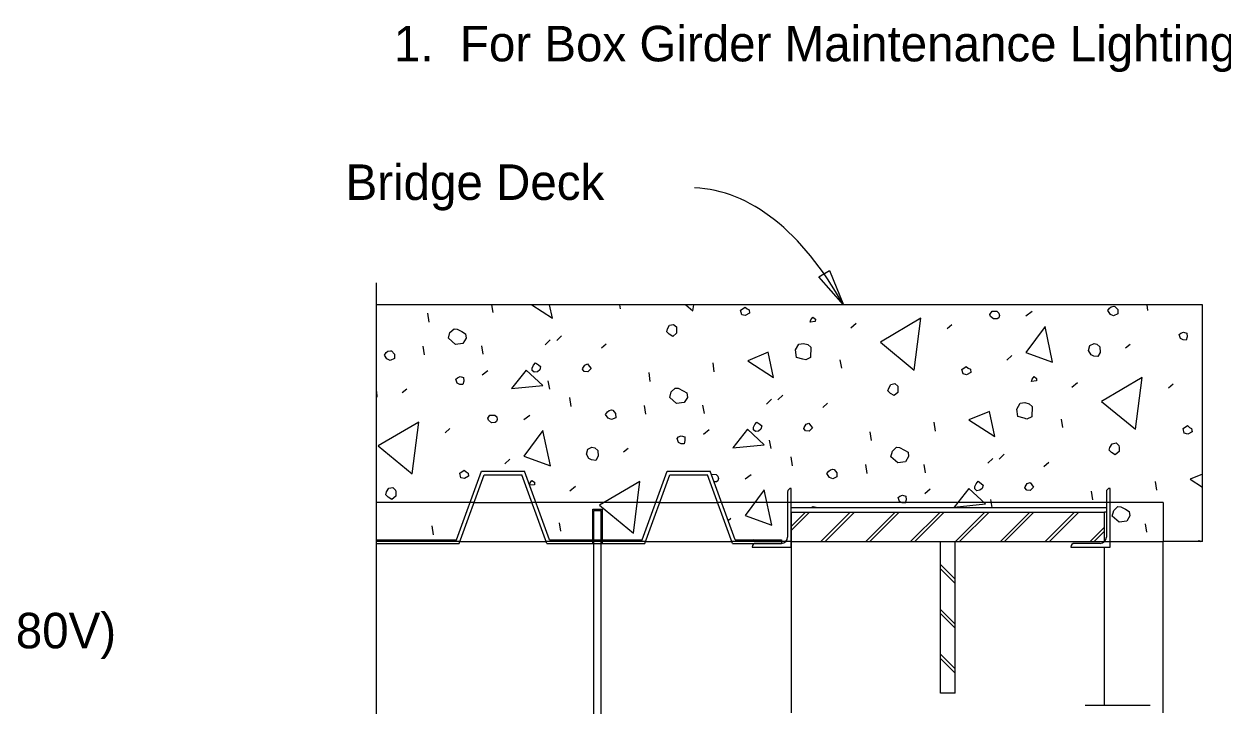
# Model space of a CAD drawing. Extents: x 0 to 30.8, y 0 to 21.2.
# Drawn here: x 21.15 to 26.25, y 6.83 to 9.73 of the extents above; entities that cross this region are included whole.
import ezdxf

# ---------------------------------------------------------------- set-up
doc = ezdxf.new("R2010")
doc.units = 0
for name, color, linetype in [('Dimension', 7, 'Continuous'), ('Lighting', 7, 'Continuous'), ('Miscellaneous', 7, 'Continuous'), ('SteelGirder', 7, 'Continuous'), ('SteelGirder_h', 7, 'Continuous'), ('SupstrConc', 7, 'Continuous'), ('TextStructures', 7, 'Continuous')]:
    doc.layers.add(name, color=color, linetype=linetype)

msp = doc.modelspace()

# ---------------------------------------------------------------- linework, layer by layer
at = {"layer": 'Dimension'}
msp.add_lwpolyline([(24.6432, 8.5353), (24.5386, 8.6542), (24.5836, 8.682)], close=True, dxfattribs=at)
msp.add_lwpolyline([(22.6555, 6.3623), (22.6555, 8.629)], dxfattribs=at)
msp.add_ellipse((23.8981, 6.6665), major_axis=(-0.1111, -2.3674), ratio=0.464296, start_param=2.502126, end_param=3.141581, dxfattribs=at)
at = {"layer": 'Lighting'}
msp.add_line((25.6718, 6.8313), (25.9492, 6.8313), dxfattribs=at)
at = {"layer": 'Miscellaneous'}
for p, q in [((23.1517, 8.5027), (23.147, 8.5353)), ((23.6941, 8.5179), (23.6911, 8.5353)), ((25.939, 8.5116), (25.9355, 8.5353)), ((22.8793, 8.4618), (22.8739, 8.4995)), ((25.4459, 8.5066), (25.4201, 8.4876)), ((24.6973, 8.4561), (24.6739, 8.4365)), ((25.1047, 8.4505), (25.0844, 8.4326)), ((23.3947, 8.3858), (23.3738, 8.3656)), ((23.4435, 8.4038), (23.4226, 8.3836)), ((23.6333, 8.3685), (23.613, 8.3506)), ((25.8637, 8.3661), (25.8441, 8.3507)), ((22.86, 8.3221), (22.8546, 8.3598)), ((23.1093, 8.3252), (23.1032, 8.3604)), ((25.3596, 8.32), (25.3387, 8.2998)), ((24.0935, 8.2504), (24.088, 8.2881)), ((24.6359, 8.2655), (24.6298, 8.3008)), ((23.1293, 8.2551), (23.1059, 8.2355)), ((23.393, 8.1767), (23.3869, 8.2119)), ((23.8211, 8.2095), (23.8157, 8.2472)), ((22.7848, 8.1766), (22.7651, 8.1611)), ((25.6391, 8.2038), (25.6157, 8.1841)), ((26.0465, 8.1981), (26.0262, 8.1803)), ((23.4846, 8.103), (23.4791, 8.1406)), ((24.3365, 8.1335), (24.3155, 8.1132)), ((24.3853, 8.1515), (24.3643, 8.1312)), ((24.5751, 8.1161), (24.5548, 8.0983)), ((23.3087, 8.0647), (23.2829, 8.0457)), ((23.8018, 8.0697), (23.7963, 8.1074)), ((24.0511, 8.0728), (24.045, 8.1081)), ((22.9675, 8.0086), (22.9472, 7.9907)), ((25.0352, 7.998), (25.0298, 8.0357)), ((25.5776, 8.0132), (25.5716, 8.0484)), ((24.0711, 8.0027), (24.0477, 7.9831)), ((24.3348, 7.9243), (24.3287, 7.9596)), ((24.7629, 7.9571), (24.7574, 7.9948)), ((23.7265, 7.9242), (23.7069, 7.9088)), ((23.2224, 7.8781), (23.2015, 7.8579)), ((24.4263, 7.8506), (24.4209, 7.8883)), ((24.7435, 7.8174), (24.7381, 7.8551)), ((24.9928, 7.8205), (24.9868, 7.8557)), ((25.2783, 7.8811), (25.2573, 7.8609)), ((25.3271, 7.8991), (25.3061, 7.8789)), ((25.5169, 7.8638), (25.4966, 7.8459)), ((22.996, 7.5353), (23.1022, 7.8271)), ((23.007, 7.5197), (23.1132, 7.8115)), ((23.1022, 7.8271), (23.2855, 7.8271)), ((23.1132, 7.8115), (23.2746, 7.8115)), ((23.3808, 7.5197), (23.2746, 7.8115)), ((23.3917, 7.5353), (23.2855, 7.8271)), ((23.7865, 7.5353), (23.8927, 7.8271)), ((23.7974, 7.5197), (23.9036, 7.8115)), ((23.8927, 7.8271), (24.076, 7.8271)), ((23.9036, 7.8115), (24.0651, 7.8115)), ((24.1712, 7.5197), (24.0651, 7.8115)), ((24.1822, 7.5353), (24.076, 7.8271)), ((24.2504, 7.8123), (24.2246, 7.7934)), ((23.5019, 7.7619), (23.4785, 7.7422)), ((24.4212, 7.5041), (24.4212, 7.7541)), ((25.7779, 7.5041), (25.7779, 7.7541)), ((25.977, 7.7457), (25.9716, 7.7834)), ((24.4056, 7.7385), (24.4056, 7.5458)), ((25.0129, 7.7504), (24.9895, 7.7308)), ((25.2764, 7.6731), (25.2705, 7.7072)), ((25.7046, 7.7048), (25.6992, 7.7425)), ((25.7623, 7.7384), (25.7623, 7.5457)), ((24.4212, 7.5922), (24.4814, 7.6523)), ((24.4212, 7.5745), (24.4991, 7.6523)), ((24.4213, 7.6731), (25.7623, 7.6731)), ((24.5473, 7.5273), (24.6723, 7.6523)), ((24.565, 7.5273), (24.69, 7.6523)), ((24.7382, 7.5273), (24.8632, 7.6523)), ((24.7559, 7.5273), (24.8809, 7.6523)), ((24.9291, 7.5273), (25.0541, 7.6523)), ((24.9468, 7.5273), (25.0718, 7.6523)), ((25.1201, 7.5273), (25.2451, 7.6523)), ((25.1377, 7.5273), (25.2627, 7.6523)), ((25.311, 7.5273), (25.436, 7.6523)), ((25.3287, 7.5273), (25.4537, 7.6523)), ((25.5019, 7.5273), (25.6269, 7.6523)), ((25.5196, 7.5273), (25.6446, 7.6523)), ((25.7623, 7.6523), (25.7547, 7.6523)), ((23.4404, 7.5713), (23.4344, 7.6065)), ((24.1642, 7.6258), (24.1531, 7.6151)), ((25.9346, 7.5681), (25.9285, 7.6034)), ((22.898, 7.5561), (22.8926, 7.5938)), ((25.6928, 7.5273), (25.7546, 7.5891)), ((25.7105, 7.5273), (25.7546, 7.5715)), ((22.6555, 7.5353), (22.996, 7.5353)), ((22.6555, 7.5197), (23.007, 7.5197)), ((23.3808, 7.5197), (23.7974, 7.5197)), ((23.3917, 7.5353), (23.7865, 7.5353)), ((24.1712, 7.5197), (24.3795, 7.5197)), ((24.1822, 7.5353), (24.3795, 7.5353)), ((24.2545, 7.5041), (24.4212, 7.5041)), ((24.3795, 7.5197), (24.2702, 7.5197)), ((24.3795, 7.5353), (24.3795, 7.5197)), ((25.6113, 7.5041), (25.7779, 7.5041)), ((25.7363, 7.5197), (25.6269, 7.5197)), ((25.1192, 7.3668), (25.0568, 7.4292)), ((25.1192, 7.3491), (25.0568, 7.4115)), ((25.1192, 7.1759), (25.0568, 7.2383)), ((25.1192, 7.1582), (25.0568, 7.2206)), ((25.1192, 6.9849), (25.0568, 7.0473)), ((25.1192, 6.9673), (25.0568, 7.0297))]:
    msp.add_line(p, q, dxfattribs=at)
for points in [[(23.3167, 8.5353), (23.4042, 8.4791)], [(23.4042, 8.4791), (23.392, 8.5353)], [(23.9722, 8.5353), (24.0026, 8.5102)], [(24.0026, 8.5102), (24.0058, 8.5353)], [(24.2432, 8.5001), (24.2248, 8.4895), (24.2103, 8.4934), (24.2052, 8.5129), (24.2242, 8.5259), (24.2326, 8.5185), (24.2416, 8.5135), (24.2432, 8.5001), (24.2445, 8.505)], [(25.8105, 8.515), (25.8108, 8.4968), (25.793, 8.4886), (25.7792, 8.4949), (25.7679, 8.5109), (25.776, 8.5216), (25.7828, 8.5276), (25.7937, 8.5298), (25.7986, 8.5285), (25.8105, 8.515)], [(24.5234, 8.4639), (24.5021, 8.4618), (24.5047, 8.4715), (24.5128, 8.4823), (24.5235, 8.4742), (24.5234, 8.4639)], [(24.9444, 8.2579), (24.9724, 8.4782), (24.8002, 8.3768), (24.9444, 8.2579)], [(25.3041, 8.4799), (25.298, 8.4763), (25.2822, 8.4754), (25.2696, 8.4865), (25.2668, 8.495), (25.2755, 8.5082), (25.2961, 8.5079), (25.3045, 8.5005), (25.3067, 8.4895), (25.3041, 8.4799)], [(23.0371, 8.3937), (23.0233, 8.3715), (22.9911, 8.3672), (22.9618, 8.3931), (22.9683, 8.4173), (22.9856, 8.4334), (22.9983, 8.4325), (23.0187, 8.4219), (23.0343, 8.4125), (23.0371, 8.3937)], [(23.9328, 8.4332), (23.9331, 8.415), (23.9165, 8.4013), (23.9009, 8.4107), (23.8908, 8.4212), (23.894, 8.4332), (23.9033, 8.4488), (23.9198, 8.4522), (23.9323, 8.4411), (23.9328, 8.4332)], [(25.5332, 8.2917), (25.5012, 8.4426), (25.4199, 8.3324), (25.5332, 8.2917)], [(26.1057, 8.3997), (26.1018, 8.3852), (26.0891, 8.386), (26.0776, 8.3917), (26.0719, 8.4087), (26.0786, 8.4147), (26.0902, 8.4193), (26.1047, 8.4155), (26.1057, 8.3997)], [(24.5046, 8.355), (24.5032, 8.3114), (24.4824, 8.3014), (24.4704, 8.3047), (24.4438, 8.3118), (24.4395, 8.344), (24.4538, 8.3686), (24.4727, 8.3713), (24.492, 8.3662), (24.5046, 8.355)], [(25.7344, 8.3568), (25.7358, 8.3331), (25.7258, 8.3151), (25.7083, 8.3172), (25.6969, 8.3229), (25.6862, 8.3412), (25.6921, 8.363), (25.7098, 8.3712), (25.7219, 8.3679), (25.7344, 8.3568)], [(22.7315, 8.3254), (22.7318, 8.3072), (22.7141, 8.2991), (22.7002, 8.3054), (22.689, 8.3213), (22.697, 8.3321), (22.7038, 8.338), (22.7147, 8.3403), (22.7196, 8.339), (22.7315, 8.3254)], [(24.3459, 8.2267), (24.3229, 8.3338), (24.2356, 8.2977), (24.3459, 8.2267)], [(23.3501, 8.258), (23.3403, 8.2503), (23.3269, 8.2487), (23.3185, 8.2561), (23.3187, 8.2664), (23.3244, 8.2779), (23.3324, 8.2887), (23.3456, 8.2799), (23.354, 8.2725), (23.3501, 8.258)], [(23.5691, 8.2641), (23.5549, 8.2497), (23.5398, 8.2512), (23.5321, 8.261), (23.5334, 8.2659), (23.5421, 8.2791), (23.5537, 8.2837), (23.5614, 8.2739), (23.5691, 8.2641)], [(25.185, 8.2478), (25.1666, 8.2372), (25.1521, 8.2411), (25.147, 8.2606), (25.166, 8.2736), (25.1744, 8.2662), (25.1834, 8.2612), (25.185, 8.2478), (25.1863, 8.2526)], [(23.0267, 8.2101), (23.0228, 8.1956), (23.0101, 8.1964), (22.9987, 8.2021), (22.9929, 8.2192), (22.9996, 8.2251), (23.0112, 8.2298), (23.0257, 8.2259), (23.0267, 8.2101)], [(23.3636, 8.1923), (23.2931, 8.2578), (23.2305, 8.1788), (23.3636, 8.1923)], [(25.4651, 8.2115), (25.4439, 8.2095), (25.4465, 8.2191), (25.4545, 8.2299), (25.4653, 8.2218), (25.4651, 8.2115)], [(25.8862, 8.0055), (25.9141, 8.2258), (25.742, 8.1244), (25.8862, 8.0055)], [(22.6555, 8.1661), (22.6569, 8.1436), (22.6555, 8.1411)], [(23.9788, 8.1413), (23.9651, 8.1191), (23.9329, 8.1148), (23.9036, 8.1408), (23.9101, 8.1649), (23.9273, 8.181), (23.9401, 8.1802), (23.9605, 8.1695), (23.9761, 8.1602), (23.9788, 8.1413)], [(24.8746, 8.1808), (24.8749, 8.1626), (24.8583, 8.149), (24.8427, 8.1583), (24.8325, 8.1688), (24.8358, 8.1809), (24.8451, 8.1965), (24.8616, 8.1999), (24.8741, 8.1887), (24.8746, 8.1808)], [(25.4463, 8.1027), (25.445, 8.0591), (25.4242, 8.0491), (25.4121, 8.0523), (25.3856, 8.0595), (25.3813, 8.0917), (25.3956, 8.1163), (25.4145, 8.119), (25.4338, 8.1138), (25.4463, 8.1027)], [(23.1669, 8.038), (23.1608, 8.0344), (23.145, 8.0335), (23.1325, 8.0446), (23.1296, 8.0531), (23.1383, 8.0663), (23.1589, 8.066), (23.1673, 8.0586), (23.1695, 8.0476), (23.1669, 8.038)], [(23.6733, 8.0731), (23.6736, 8.0549), (23.6558, 8.0467), (23.642, 8.053), (23.6307, 8.069), (23.6388, 8.0797), (23.6456, 8.0857), (23.6565, 8.0879), (23.6614, 8.0866), (23.6733, 8.0731)], [(25.2877, 7.9744), (25.2647, 8.0815), (25.1773, 8.0454), (25.2877, 7.9744)], [(22.8072, 7.816), (22.8352, 8.0363), (22.6631, 7.9348), (22.8072, 7.816)], [(24.2919, 8.0057), (24.2821, 7.998), (24.2687, 7.9964), (24.2603, 8.0038), (24.2605, 8.0141), (24.2661, 8.0255), (24.2742, 8.0363), (24.2874, 8.0276), (24.2958, 8.0202), (24.2919, 8.0057)], [(24.5109, 8.0117), (24.4967, 7.9974), (24.4816, 7.9989), (24.4739, 8.0087), (24.4752, 8.0135), (24.4839, 8.0267), (24.4955, 8.0314), (24.5032, 8.0215), (24.5109, 8.0117)], [(26.1268, 7.9954), (26.1084, 7.9848), (26.0939, 7.9887), (26.0888, 8.0082), (26.1078, 8.0212), (26.1162, 8.0138), (26.1252, 8.0088), (26.1268, 7.9954), (26.1281, 8.0003)], [(23.396, 7.8497), (23.364, 8.0007), (23.2827, 7.8905), (23.396, 7.8497)], [(23.9685, 7.9578), (23.9646, 7.9433), (23.9519, 7.9441), (23.9404, 7.9497), (23.9347, 7.9668), (23.9414, 7.9728), (23.953, 7.9774), (23.9675, 7.9735), (23.9685, 7.9578)], [(24.3053, 7.94), (24.2349, 8.0054), (24.1723, 7.9264), (24.3053, 7.94)], [(23.5972, 7.9149), (23.5986, 7.8912), (23.5886, 7.8732), (23.5711, 7.8753), (23.5597, 7.881), (23.549, 7.8993), (23.5549, 7.9211), (23.5726, 7.9292), (23.5847, 7.926), (23.5972, 7.9149)], [(24.9206, 7.889), (24.9069, 7.8668), (24.8747, 7.8625), (24.8454, 7.8884), (24.8519, 7.9126), (24.8691, 7.9287), (24.8818, 7.9278), (24.9023, 7.9172), (24.9179, 7.9078), (24.9206, 7.889)], [(25.8164, 7.9285), (25.8167, 7.9103), (25.8001, 7.8966), (25.7844, 7.906), (25.7743, 7.9165), (25.7775, 7.9285), (25.7869, 7.9441), (25.8033, 7.9475), (25.8159, 7.9364), (25.8164, 7.9285)], [(23.0478, 7.8059), (23.0294, 7.7953), (23.0149, 7.7992), (23.0098, 7.8186), (23.0288, 7.8317), (23.0372, 7.8242), (23.0462, 7.8192), (23.0478, 7.8059), (23.0491, 7.8107)], [(24.0808, 7.814), (24.1007, 7.8136), (24.109, 7.8062), (24.1113, 7.7953), (24.1087, 7.7856)], [(24.615, 7.8207), (24.6153, 7.8025), (24.5976, 7.7944), (24.5838, 7.8007), (24.5725, 7.8166), (24.5806, 7.8274), (24.5873, 7.8333), (24.5983, 7.8356), (24.6031, 7.8343), (24.615, 7.8207)], [(26.1713, 7.8146), (26.1191, 7.793), (26.1713, 7.7595)], [(22.7374, 7.7389), (22.7377, 7.7207), (22.7211, 7.7071), (22.7055, 7.7164), (22.6953, 7.7269), (22.6986, 7.739), (22.7079, 7.7546), (22.7244, 7.758), (22.7369, 7.7468), (22.7374, 7.7389)], [(23.3069, 7.7684), (23.3093, 7.7772), (23.3173, 7.788), (23.3281, 7.7799), (23.3279, 7.7696)], [(23.3279, 7.7696), (23.3072, 7.7676)], [(23.749, 7.5636), (23.7769, 7.7839), (23.6048, 7.6825), (23.749, 7.5636)], [(24.1087, 7.7856), (24.1026, 7.7821), (24.0926, 7.7815)], [(25.2471, 7.6876), (25.1767, 7.7531), (25.1141, 7.6741), (25.2471, 7.6876)], [(25.2337, 7.7533), (25.2238, 7.7456), (25.2105, 7.744), (25.2021, 7.7514), (25.2023, 7.7617), (25.2079, 7.7732), (25.216, 7.784), (25.2292, 7.7752), (25.2375, 7.7678), (25.2337, 7.7533)], [(25.4527, 7.7594), (25.4385, 7.745), (25.4234, 7.7465), (25.4156, 7.7563), (25.4169, 7.7612), (25.4256, 7.7744), (25.4372, 7.779), (25.445, 7.7692), (25.4527, 7.7594)], [(24.3378, 7.5974), (24.3058, 7.7483), (24.2245, 7.6381), (24.3378, 7.5974)], [(24.9102, 7.7054), (24.9064, 7.6909), (24.8936, 7.6917), (24.8822, 7.6974), (24.8764, 7.7145), (24.8832, 7.7204), (24.8948, 7.7251), (24.9093, 7.7212), (24.9102, 7.7054)], [(24.5062, 7.6731), (24.5144, 7.6769), (24.5264, 7.6737), (24.5271, 7.6731)], [(25.8624, 7.6366), (25.8487, 7.6144), (25.8165, 7.6101), (25.7872, 7.6361), (25.7936, 7.6602), (25.8109, 7.6763), (25.8236, 7.6755), (25.8441, 7.6648), (25.8597, 7.6555), (25.8624, 7.6366)], [(24.2589, 7.5353), (24.2591, 7.5357), (24.2596, 7.5353)], [(26.1546, 7.5273), (26.1578, 7.5316), (26.1643, 7.5273)]]:
    msp.add_lwpolyline(points, dxfattribs=at)
for centre, radius, start, end in [((24.4212, 7.7385), 0.0156, 90.0047, 180.0047), ((25.7779, 7.7384), 0.0156, 90.0047, 180.0047), ((24.2702, 7.5041), 0.0156, 90.0047, 180.0047), ((24.3795, 7.5458), 0.026, 270.0047, 0.0047), ((25.6269, 7.5041), 0.0156, 90.0047, 180.0047), ((25.7363, 7.5457), 0.026, 270.0047, 0.0047)]:
    msp.add_arc(centre, radius, start, end, dxfattribs=at)
at = {"layer": 'SteelGirder'}
for p, q in [((23.0704, 7.6941), (23.3173, 7.6941)), ((23.5761, 7.6655), (23.6177, 7.6655)), ((23.5761, 7.5197), (23.5761, 7.6655)), ((23.5813, 6.6001), (23.5813, 7.6603)), ((23.5813, 7.6603), (23.6125, 7.6603)), ((23.6125, 6.6001), (23.6125, 7.6603)), ((23.6177, 7.5197), (23.6177, 7.6655)), ((23.8609, 7.6941), (24.1078, 7.6941)), ((24.4213, 7.6523), (25.7547, 7.6523)), ((24.4213, 7.5041), (24.4213, 7.6523)), ((25.7547, 7.5273), (25.7547, 7.6523)), ((23.0097, 7.5274), (23.378, 7.5274)), ((23.8002, 7.5274), (24.1685, 7.5274)), ((24.4213, 7.5273), (26.0047, 7.5273)), ((24.4213, 6.798), (24.4213, 7.5041)), ((25.0568, 6.8813), (25.0568, 7.5273)), ((25.1192, 6.8813), (25.1192, 7.5273)), ((25.7547, 6.8313), (25.7547, 7.5041)), ((26.0047, 6.7981), (26.0047, 7.5273)), ((25.1192, 6.8813), (25.0568, 6.8813))]:
    msp.add_line(p, q, dxfattribs=at)
at = {"layer": 'SteelGirder_h'}
for p, q in [((23.0704, 7.6941), (22.6555, 7.6941)), ((23.8609, 7.6941), (23.3173, 7.6941)), ((26.0047, 7.6941), (24.1078, 7.6941)), ((26.0047, 7.6941), (26.0047, 7.5273)), ((23.0097, 7.5274), (22.6555, 7.5274)), ((23.8002, 7.5274), (23.378, 7.5274)), ((24.4213, 7.5274), (24.1685, 7.5274))]:
    msp.add_line(p, q, dxfattribs=at)
at = {"layer": 'SupstrConc'}
for p, q in [((26.1713, 8.5353), (22.6555, 8.5353)), ((26.1713, 7.5273), (26.1713, 8.5353)), ((26.1713, 7.5273), (26.0047, 7.5273))]:
    msp.add_line(p, q, dxfattribs=at)

# ---------------------------------------------------------------- texts
at = {"layer": 'Dimension'}
msp.add_text('1.  For Box Girder Maintenance Lighting Notes see Sheet 1.', height=0.1512, dxfattribs=at).set_placement((22.7296, 9.5722))
at = {"layer": 'TextStructures'}
for s, p in [('Bridge Deck', (22.5237, 8.9822)), ('Conduit (480V)', (20.1873, 7.0728))]:
    msp.add_text(s, height=0.1512, dxfattribs=at).set_placement(p)

doc.saveas('drawing.dxf')
